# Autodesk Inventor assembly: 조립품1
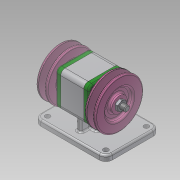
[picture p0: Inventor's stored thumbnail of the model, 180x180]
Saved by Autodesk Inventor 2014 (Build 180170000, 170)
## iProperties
Created: 2020-11
Part Number: 조립품1
Document SubType Name: Assembly
Designer: NET
Author: NET
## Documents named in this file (10)
- C:\Users\NET\Desktop\701106V1046\조립품1.iam
- C:\Users\NET\Desktop\701106V1046\V-벨트풀리.ipt
- C:\Users\NET\Desktop\701106V1046\너트 M10x1.ipt
- C:\Users\NET\Desktop\701106V1046\베어링 6004.ipt
- C:\Users\NET\Desktop\701106V1046\볼트 M4.ipt
- C:\Users\NET\Desktop\701106V1046\부품2.ipt
- C:\Users\NET\Desktop\701106V1046\오일 실 17 30 5.ipt
- C:\Users\NET\Desktop\701106V1046\키 5 x 5 x 12.ipt
- C:\Users\NET\Desktop\701106V1046\축.ipt
- C:\Users\NET\Desktop\701106V1046\커버.ipt
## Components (2 placed, 1 different names)
1. V-벨트풀리:1
2. V-벨트풀리:2
